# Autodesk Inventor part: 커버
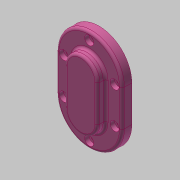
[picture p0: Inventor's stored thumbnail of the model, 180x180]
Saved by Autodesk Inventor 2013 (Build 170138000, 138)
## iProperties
Created: 2019-03
Part Number: 커버
Material: 알루미늄 6061
Document SubType Name: Modeling
Designer: mduedu
Density: 1 g/cm^3
Author: mduedu
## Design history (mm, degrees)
sketch "스케치1"
  geometry: L1 (-62, 40)-(62, 40); L2 (62, 40)-(62, -40); L3 (62, -40)-(-62, -40); L4 (-62, -40)-(-62, 40); L5 (-62, 40)-(62, -40); L6 (62, 40)-(-62, -40); 1 further point
  constraints: 12 end point, 2 midpoint, 2 parallel, 1 horizontal, 1 perpendicular
  dimensions: "d59" = 124 distance of L2.end L3.end; "d60" = 80 distance of L1.end L2.end
extrude "돌출1" new body sketch "스케치1" distance "d4" = 12; taper "d5" = 0 deg
fillet "모깎기4"
fillet "모깎기5"
sketch "스케치2"
  geometry: L1 (-20, -22)-(20, -22); L2 (20, -22)-(20, 22); L3 (20, 22)-(-20, 22); L4 (-20, 22)-(-20, -22); L5 (-20, -22)-(20, 22); L6 (20, -22)-(-20, 22); 3 further points
  constraints: 12 end point, 4 midpoint, 2 horizontal alignment, 2 parallel, 1 horizontal, 1 perpendicular, 4 other
  dimensions: "d6" = 40 distance between parallel lines of L2 L4; "d8" = 44 distance between parallel lines of L1 L3
extrude "돌출2" join sketch "스케치2" distance "d9" = 10; taper "d10" = 0 deg
fillet "모깎기2" dims "d12" = 3
sketch "스케치3"
  geometry: L1 (-31, -22)-(31, -22); L2 (31, -22)-(31, 22); L3 (31, 22)-(-31, 22); L4 (-31, 22)-(-31, -22); L5 (-31, -22)-(31, 22); L6 (31, -22)-(-31, 22); A1 r 31 centre (0, 22) between (31, 22) and (0, 53); A2 r 31 centre (0, -22) between (31, -22) and (0, -53); 7 further points
  constraints: 12 end point, 6 midpoint, 4 coincident, 4 point on circle, 2 centre point, 2 parallel, 2 vertical alignment, 1 horizontal, 1 perpendicular
  dimensions: "d76" = 44 distance between parallel lines of L1 L3; "d78" = 62 distance between parallel lines of L2 L4
hole "구멍2" sketch "스케치3" at (0, 53), (31, 22), (31, -22), (-31, -22), (-31, 22), (0, -53) diameter "d28" = 5.5; stored, may be unused: countersink angle "d32" = 90 deg, drill point angle "d34" = 118 deg; dims "d29" = 6, "d30" = 4, "d31" = 2, "d33" = 8
sketch "스케치10"
  geometry: L1 (40, -22)-(40, 22) reference; L2 (-40, 22)-(-40, -22) reference; L3 (23, -22)-(23, 22) reference; L4 (-23, 22)-(-23, -22) reference; C1 r 2.75 at (-31, 22) reference; C2 r 2.75 at (31, -22) reference; C3 r 2.75 at (0, 53) reference; C4 r 2.75 at (31, 22) reference; C5 r 2.75 at (-31, -22) reference; C6 r 2.75 at (0, -53) reference; A1 r 40 centre (0, -22) between (-40, -22) and (40, -22) reference; A2 r 40 centre (0, 22) between (40, 22) and (-40, 22) reference; A3 r 23 centre (0, -22) between (-23, -22) and (23, -22) reference; A4 r 23 centre (0, 22) between (23, 22) and (-23, 22) reference; 7 further points
  constraints: 6 coincident
hole "구멍5" sketch "스케치10" at (0, 53), (31, 22), (31, -22), (0, -53), (-31, -22), (-31, 22) diameter "d79" = 11; stored, may be unused: countersink angle "d83" = 90 deg, drill point angle "d85" = 0 deg; dims "d80" = 6, "d81" = 4, "d82" = 2, "d84" = 5.4
fillet "모깎기3" dims "d68" = 3
sketch "스케치6"
  geometry: C1 r 12.5 at (0, 22); 1 further point
  constraints: 1 centre point, 1 vertical alignment
  dimensions: "d43" = 25 diameter of C1; "d45" = 22 distance of C1.centre point (0, 0)
extrude "돌출5" cut sketch "스케치6" distance "d47" = 15; taper "d48" = 0 deg
node "솔리드1"
mirror "대칭1"
node "투영된 루프5"
